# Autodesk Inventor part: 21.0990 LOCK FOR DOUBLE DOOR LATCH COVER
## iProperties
Created: 2007-03
Part Number: 21.0990 LOCK FOR DOUBLE DOOR LATCH COVER
Material: Steel
Document SubType Name: Modeling
Designer: Andy Moles
Density: 7.85 g/cm^3
Author: Andy Moles
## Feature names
1. Base1
2. Extrusion1
3. Extrusion2
